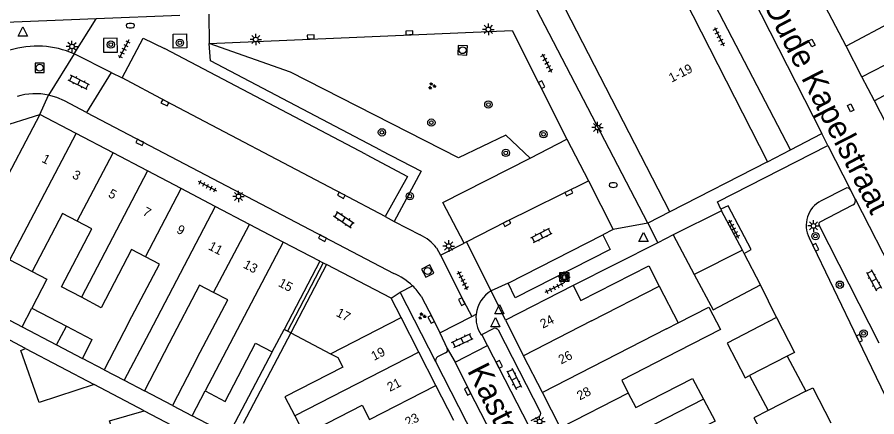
# Model space of a CAD drawing. Extents: x 132999 to 136000, y 398499 to 400501.
# Drawn here: x 133414.1 to 133507.8, y 398557.3 to 398600.8 of the extents above; entities that cross this region are included whole.
import ezdxf

# ---------------------------------------------------------------- set-up
doc = ezdxf.new("R2010")
doc.units = 0
for name, color, linetype in [('gg-afsc-erfafscheiding', 7, 'Continuous'), ('gg-afsc-muur', 7, 'Continuous'), ('gg-anno-huisnummerreeks BGT', 7, 'Continuous'), ('gg-anno-openbare ruimte label', 7, 'Continuous'), ('gg-bbg-bijgebouw', 7, 'Continuous'), ('gg-bbg-gedigitaliseerde bebouwing', 7, 'Continuous'), ('gg-bbg-gedigitaliseerde bebouwing onder overbouw', 7, 'Continuous'), ('gg-bbg-gedigitaliseerde bijgebouw', 7, 'Continuous'), ('gg-bbg-gedigitaliseerde overbouw', 7, 'Continuous'), ('gg-bbg-hoofdgebouw', 7, 'Continuous'), ('gg-bbg-pand overbouw', 7, 'Continuous'), ('gg-bbg-tussenscheiding', 7, 'Continuous'), ('gg-bbg-tussenscheiding niveau 01', 7, 'Continuous'), ('gg-knt-verharding', 7, 'Continuous'), ('gg-knt-verharding nz', 7, 'Continuous'), ('gt-grn-groengrens', 7, 'Continuous'), ('gt-grn-weggrens', 7, 'Continuous'), ('gt-symb-boom', 7, 'Continuous'), ('gt-symb-brandkraan', 7, 'Continuous'), ('gt-symb-groenvak', 7, 'Continuous'), ('gt-symb-klinker verharding', 7, 'Continuous'), ('gt-symb-kolk', 7, 'Continuous'), ('gt-symb-kolk center center', 7, 'Continuous'), ('gt-symb-laadpunt elektrisch vervoer', 7, 'Continuous'), ('gt-symb-lichtmast', 7, 'Continuous'), ('gt-symb-rioolschacht', 7, 'Continuous'), ('gt-symb-tegel verharding', 7, 'Continuous'), ('gt-symb-waterafsluiter', 7, 'Continuous')]:
    doc.layers.add(name, color=color, linetype=linetype)

# ---------------------------------------------------------------- blocks, each defined once
blk = doc.blocks.new('gt0-KOLK')
at = {"layer": 'gt-symb-kolk'}
blk.add_lwpolyline([(0, 0), (0.375, 0), (0.375, 0.4), (-0.375, 0.4), (-0.375, 0), (0, 0)], dxfattribs=at)
blk = doc.blocks.new('gt0-BOOM')
at = {"layer": 'gt-symb-boom'}
for radius in [0.4, 0.2]:
    blk.add_circle((0, 0), radius, dxfattribs=at)
blk = doc.blocks.new('gt0-KL1')
at = {"layer": 'gt-symb-klinker verharding'}
for p, q in [((-1.15, 0.3), (1.15, 0.3)), ((-1, -0.3), (-1, 0.3)), ((-0.5, 0.3), (-0.5, 0.45)), ((0, -0.3), (0, 0.3)), ((0.5, 0.3), (0.5, 0.45)), ((1, -0.3), (1, 0.3)), ((-1.15, -0.3), (1.15, -0.3)), ((-0.5, -0.45), (-0.5, -0.3)), ((0.5, -0.45), (0.5, -0.3))]:
    blk.add_line(p, q, dxfattribs=at)
blk = doc.blocks.new('gt0-KOLKCC')
at = {"layer": 'gt-symb-kolk center center'}
blk.add_lwpolyline([(-0.375, 0.2), (0.375, 0.2), (0.375, -0.2), (-0.375, -0.2)], close=True, dxfattribs=at)
blk = doc.blocks.new('gt0-LMAST')
at = {"layer": 'gt-symb-lichtmast'}
for p, q in [((-0.182, 0.173), (-0.447, 0.438)), ((-0.005, 0.246), (-0.005, 0.621)), ((0.172, 0.173), (0.437, 0.438)), ((-0.255, -0.004), (-0.63, -0.004)), ((-0.182, -0.181), (-0.447, -0.446)), ((-0.005, -0.254), (-0.005, -0.629)), ((0.437, -0.446), (0.172, -0.181)), ((0.245, -0.004), (0.62, -0.004))]:
    blk.add_line(p, q, dxfattribs=at)
blk.add_circle((-0.005, -0.004), 0.25, dxfattribs=at)
blk = doc.blocks.new('gt0-TEG1')
at = {"layer": 'gt-symb-tegel verharding'}
for p, q in [((-1.125, 0), (1.125, 0)), ((-0.9, -0.25), (-0.9, 0.25)), ((-0.45, -0.25), (-0.45, 0.25)), ((0, -0.25), (0, 0.25)), ((0.45, -0.25), (0.45, 0.25)), ((0.9, -0.25), (0.9, 0.25))]:
    blk.add_line(p, q, dxfattribs=at)
blk = doc.blocks.new('gt0-BR')
at = {"layer": 'gt-symb-brandkraan'}
for centre, radius, start, end in [((-0.244, 0), 0.206, 107.56694, 252.43307), ((0.599, -2.664), 3, 106.89205, 107.56694), ((0, -0.691), 0.938, 73.10799, 106.89205), ((-0.599, -2.664), 3, 72.43309, 73.10799), ((0.244, 0), 0.206, 287.56695, 72.43309), ((0.599, 2.664), 3, 252.43307, 253.10797), ((0, 0.691), 0.938, 253.10797, 286.89206), ((-0.599, 2.664), 3, 286.89206, 287.56695)]:
    blk.add_arc(centre, radius, start, end, dxfattribs=at)
blk = doc.blocks.new('gt0-LEV')
at = {"layer": 'gt-symb-laadpunt elektrisch vervoer'}
blk.add_lwpolyline([(-0.486, 0.501), (0.486, 0.501), (0.486, -0.499), (-0.486, -0.499)], close=True, dxfattribs=at)
for centre, radius in [((0, 0), 0.393), ((-0.186, 0), 0.0566), ((0.186, 0), 0.0566)]:
    blk.add_circle(centre, radius, dxfattribs=at)
blk = doc.blocks.new('gt0-WAFSL')
at = {"layer": 'gt-symb-waterafsluiter'}
for p, q in [((-0.5, -0.333), (0, 0.667)), ((0, 0.667), (0.5, -0.333)), ((0.5, -0.333), (-0.5, -0.333))]:
    blk.add_line(p, q, dxfattribs=at)
blk = doc.blocks.new('gt0-RS')
at = {"layer": 'gt-symb-rioolschacht'}
blk.add_lwpolyline([(-0.5, -0.5), (0.5, -0.5), (0.5, 0.5), (-0.5, 0.5)], close=True, dxfattribs=at)
blk.add_circle((0, 0), 0.375, dxfattribs=at)
blk = doc.blocks.new('gt0-GRVAK')
at = {"layer": 'gt-symb-groenvak'}
for p, q in [((-0.11, 0.189), (-0.228, 0.24)), ((-0.182, 0.153), (0.088, 0.153)), ((-0.091, 0.211), (-0.156, 0.322)), ((-0.047, 0.214), (-0.047, 0.393)), ((-0.004, 0.211), (0.061, 0.322)), ((0.015, 0.189), (0.133, 0.24)), ((0.262, -0.052), (0.197, 0.059)), ((0.305, -0.049), (0.305, 0.13)), ((0.349, -0.052), (0.414, 0.059)), ((-0.245, -0.228), (-0.363, -0.177)), ((-0.318, -0.264), (-0.047, -0.264)), ((-0.226, -0.206), (-0.291, -0.095)), ((-0.183, -0.203), (-0.183, -0.024)), ((-0.139, -0.206), (-0.074, -0.095)), ((-0.12, -0.228), (-0.002, -0.177)), ((0.243, -0.074), (0.125, -0.023)), ((0.17, -0.11), (0.441, -0.11)), ((0.368, -0.074), (0.486, -0.023))]:
    blk.add_line(p, q, dxfattribs=at)

msp = doc.modelspace()

# ---------------------------------------------------------------- linework, layer by layer
at = {"layer": 'gg-afsc-erfafscheiding'}
for p, q in [((133496.864, 398568.116), (133495.101, 398571.685)), ((133415.05, 398564.747), (133412.188, 398566.229)), ((133443.93, 398566.44), (133438.756, 398556.569)), ((133423.598, 398562.427), (133421.228, 398563.669)), ((133427.963, 398557.961), (133422.517, 398560.804)), ((133431.042, 398558.525), (133427.982, 398560.129))]:
    msp.add_line(p, q, dxfattribs=at)
msp.add_lwpolyline([(133441.908, 398564.38), (133437.152, 398555.322), (133433.201, 398557.393)], dxfattribs=at)
at = {"layer": 'gg-afsc-muur'}
for p, q in [((133485.6, 398577.111), (133483.915, 398576.258)), ((133483.915, 398576.258), (133474.71, 398571.6))]:
    msp.add_line(p, q, dxfattribs=at)
at = {"layer": 'gg-bbg-bijgebouw'}
for p, q in [((133504.434, 398597.688), (133501.806, 398602.758)), ((133506.163, 398594.351), (133504.434, 398597.688)), ((133507.525, 398591.723), (133506.163, 398594.351)), ((133508.838, 398589.189), (133507.525, 398591.723)), ((133490.88, 398579.751), (133485.6, 398577.111)), ((133493.16, 398575.439), (133490.88, 398579.751)), ((133493.329, 398575.112), (133493.16, 398575.439)), ((133495.101, 398571.685), (133493.329, 398575.112)), ((133498.4, 398564.084), (133498.034, 398563.894)), ((133498.034, 398563.894), (133500.043, 398560.076))]:
    msp.add_line(p, q, dxfattribs=at)
for points in [[(133496.864, 398568.116), (133498.838, 398564.31), (133498.4, 398564.084)], [(133500.043, 398560.076), (133500.831, 398560.459), (133502.781, 398556.636)]]:
    msp.add_lwpolyline(points, dxfattribs=at)
at = {"layer": 'gg-bbg-gedigitaliseerde bebouwing'}
for p, q in [((133482.95, 398573.761), (133484.09, 398571.541)), ((133484.09, 398571.541), (133486.141, 398567.538)), ((133426.31, 398567.607), (133423.598, 398562.427)), ((133441.908, 398564.38), (133443.2, 398566.823)), ((133443.93, 398566.44), (133448.271, 398564.168)), ((133430.694, 398565.311), (133427.982, 398560.129)), ((133433.756, 398563.709), (133431.042, 398558.525)), ((133423.598, 398562.427), (133425.786, 398561.28)), ((133425.786, 398561.28), (133427.982, 398560.129)), ((133433.201, 398557.393), (133434.628, 398560.115)), ((133431.042, 398558.525), (133433.201, 398557.393))]:
    msp.add_line(p, q, dxfattribs=at)
for points in [[(133420.672, 398578.613), (133419.071, 398579.451), (133415.761, 398573.127)], [(133421.126, 398570.319), (133418.963, 398571.451), (133422.273, 398577.775), (133420.672, 398578.613)], [(133428.11, 398574.721), (133426.599, 398575.512), (133423.288, 398569.187), (133421.126, 398570.319)], [(133426.31, 398567.607), (133429.621, 398573.93), (133428.11, 398574.721)], [(133435.536, 398570.835), (133434.006, 398571.636), (133430.694, 398565.311)], [(133433.756, 398563.709), (133437.067, 398570.033), (133435.536, 398570.835)], [(133486.141, 398567.538), (133489.5, 398569.26), (133490.761, 398566.801), (133486.153, 398564.438)], [(133434.628, 398560.115), (133436.792, 398558.981), (133440.111, 398565.321), (133441.908, 398564.38)], [(133486.153, 398564.438), (133479.997, 398561.283), (133480.712, 398559.888)], [(133448.271, 398564.168), (133449.076, 398563.747), (133449.611, 398562.703), (133443.303, 398559.47), (133444.364, 398557.399)], [(133480.712, 398559.888), (133481.528, 398558.296), (133487.722, 398561.471), (133488.912, 398559.222)], [(133488.912, 398559.222), (133490.176, 398556.831), (133483.922, 398553.626), (133484.657, 398552.192)], [(133444.364, 398557.399), (133445.426, 398555.328), (133451.732, 398558.56), (133452.532, 398557)]]:
    msp.add_lwpolyline(points, dxfattribs=at)
at = {"layer": 'gg-bbg-gedigitaliseerde bebouwing onder overbouw'}
for p, q in [((133447.09, 398574.251), (133443.2, 398566.823)), ((133447.84, 398573.911), (133443.93, 398566.44))]:
    msp.add_line(p, q, dxfattribs=at)
at = {"layer": 'gg-bbg-gedigitaliseerde bijgebouw'}
for p, q in [((133485.6, 398577.111), (133487.89, 398572.821)), ((133415.717, 398569.144), (133419.483, 398567.172)), ((133414.655, 398567.114), (133418.42, 398565.141)), ((133415.05, 398564.747), (133422.517, 398560.804)), ((133418.42, 398565.141), (133421.228, 398563.669)), ((133493.931, 398561.793), (133495.939, 398557.976)), ((133427.963, 398557.961), (133432.477, 398555.595))]:
    msp.add_line(p, q, dxfattribs=at)
for points in [[(133415.761, 398573.127), (133417.363, 398572.289), (133415.717, 398569.144)], [(133487.89, 398572.821), (133489.961, 398568.941), (133495.101, 398571.685)], [(133410.783, 398569.518), (133410.631, 398569.224), (133414.655, 398567.114)], [(133496.864, 398568.116), (133491.491, 398565.329), (133493.452, 398561.548), (133493.931, 398561.793)], [(133419.483, 398567.172), (133422.265, 398565.717), (133421.228, 398563.669)], [(133422.517, 398560.804), (133416.54, 398558.864), (133414.517, 398564.537), (133415.05, 398564.747)], [(133428.582, 398554.399), (133425.267, 398553.381), (133424.178, 398556.842), (133427.963, 398557.961)], [(133495.939, 398557.976), (133494.405, 398557.192), (133496.418, 398553.369)]]:
    msp.add_lwpolyline(points, dxfattribs=at)
at = {"layer": 'gg-bbg-gedigitaliseerde overbouw'}
for p, q in [((133443.565, 398566.632), (133443.2, 398566.823)), ((133443.93, 398566.44), (133443.565, 398566.632))]:
    msp.add_line(p, q, dxfattribs=at)
at = {"layer": 'gg-bbg-hoofdgebouw'}
for p, q in [((133485.23, 398579.62), (133471.65, 398606.041)), ((133416.597, 398590.258), (133409.788, 398577.287)), ((133420.484, 398588.218), (133416.597, 398590.258)), ((133420.552, 398588.182), (133420.484, 398588.218)), ((133424.575, 398586.07), (133420.552, 398588.182)), ((133428.338, 398584.095), (133424.575, 398586.07)), ((133495.89, 398585.081), (133485.23, 398579.62)), ((133432.008, 398582.169), (133428.338, 398584.095)), ((133435.711, 398580.225), (133432.008, 398582.169)), ((133439.431, 398578.272), (133435.711, 398580.225)), ((133443.122, 398576.334), (133439.431, 398578.272)), ((133447.09, 398574.251), (133443.122, 398576.334)), ((133454.88, 398570.221), (133447.84, 398573.911)), ((133474.71, 398571.6), (133467.32, 398567.811)), ((133455.963, 398568.107), (133454.88, 398570.221)), ((133457.895, 398564.334), (133455.963, 398568.107)), ((133467.32, 398567.811), (133469.294, 398563.96)), ((133459.754, 398560.703), (133457.895, 398564.334)), ((133471.348, 398559.955), (133469.294, 398563.96)), ((133461.702, 398556.899), (133459.754, 398560.703)), ((133473.324, 398556.101), (133471.348, 398559.955))]:
    msp.add_line(p, q, dxfattribs=at)
for points in [[(133485.137, 398608.828), (133485.22, 398608.671), (133484.14, 398608.13), (133495.89, 398585.081)], [(133474.71, 398571.6), (133475.54, 398569.971), (133482.95, 398573.761)]]:
    msp.add_lwpolyline(points, dxfattribs=at)
at = {"layer": 'gg-bbg-pand overbouw'}
for p, q in [((133447.09, 398574.251), (133447.465, 398574.081)), ((133447.465, 398574.081), (133447.84, 398573.911))]:
    msp.add_line(p, q, dxfattribs=at)
at = {"layer": 'gg-bbg-tussenscheiding'}
for p, q in [((133509.644, 398600.448), (133504.434, 398597.688)), ((133506.163, 398594.351), (133511.399, 398597.065)), ((133512.715, 398594.558), (133507.525, 398591.723)), ((133413.322, 398574.407), (133420.552, 398588.182)), ((133420.672, 398578.613), (133424.575, 398586.07)), ((133428.338, 398584.095), (133421.126, 398570.319)), ((133428.11, 398574.721), (133432.008, 398582.169)), ((133435.711, 398580.225), (133428.502, 398566.459)), ((133435.536, 398570.835), (133439.431, 398578.272)), ((133443.122, 398576.334), (133434.628, 398560.115)), ((133493.16, 398575.439), (133487.89, 398572.821)), ((133413.322, 398574.407), (133415.761, 398573.127)), ((133476.686, 398567.747), (133484.09, 398571.541)), ((133414.655, 398567.114), (133415.717, 398569.144)), ((133448.271, 398564.168), (133455.963, 398568.107)), ((133418.42, 398565.141), (133419.483, 398567.172)), ((133476.686, 398567.747), (133469.294, 398563.96)), ((133484.861, 398566.882), (133486.141, 398567.538)), ((133428.502, 398566.459), (133425.786, 398561.28)), ((133484.861, 398566.882), (133471.348, 398559.955)), ((133457.895, 398564.334), (133444.364, 398557.399)), ((133498.034, 398563.894), (133493.931, 398561.793)), ((133452.532, 398557), (133459.754, 398560.703)), ((133480.712, 398559.888), (133473.324, 398556.101)), ((133500.043, 398560.076), (133495.939, 398557.976)), ((133488.912, 398559.222), (133475.299, 398552.248))]:
    msp.add_line(p, q, dxfattribs=at)
at = {"layer": 'gg-bbg-tussenscheiding niveau 01'}
msp.add_line((133447.465, 398574.081), (133443.565, 398566.632), dxfattribs=at)
at = {"layer": 'gg-knt-verharding'}
for p, q in [((133490.822, 398609.699), (133501.806, 398588.153)), ((133498.38, 398586.391), (133487.216, 398607.907)), ((133482.83, 398578.401), (133470.246, 398602.631)), ((133431.86, 398601.031), (133422.725, 398600.661)), ((133422.725, 398600.661), (133390.33, 398599.351)), ((133452.161, 398585.892), (133430.173, 398597.438)), ((133420.345, 398596.841), (133417.553, 398592.36)), ((133424.364, 398594.835), (133420.345, 398596.841)), ((133424.364, 398594.835), (133421.683, 398590.477)), ((133424.364, 398594.835), (133425.579, 398594.225)), ((133411.38, 398588.591), (133416.597, 398590.258)), ((133421.683, 398590.477), (133455.15, 398572.92)), ((133498.38, 398586.391), (133501.806, 398588.153)), ((133502.47, 398586.851), (133501.806, 398588.153)), ((133470.038, 398585.499), (133474.031, 398587.536)), ((133474.031, 398587.536), (133476.364, 398583)), ((133476.364, 398583), (133479.076, 398577.725)), ((133504.363, 398582.192), (133501.728, 398580.843)), ((133505.421, 398581.054), (133504.93, 398582.041)), ((133501.63, 398578.543), (133505.192, 398580.404)), ((133485.23, 398579.62), (133482.83, 398578.401)), ((133490.797, 398579.933), (133490.88, 398579.751)), ((133454.224, 398579.112), (133455.219, 398578.593)), ((133455.219, 398578.593), (133458.043, 398577.12)), ((133479.076, 398577.725), (133477.951, 398577.124)), ((133508.038, 398565.332), (133501.492, 398578.176)), ((133459.81, 398575.694), (133460.256, 398574.917)), ((133460.256, 398574.917), (133462.842, 398576.23)), ((133463.101, 398576.368), (133462.842, 398576.23)), ((133465.787, 398571.027), (133463.101, 398576.368)), ((133467.614, 398571.847), (133465.787, 398571.027)), ((133455.865, 398570.892), (133457.203, 398571.576)), ((133459.754, 398563.28), (133455.865, 398570.892)), ((133460.17, 398566.446), (133463.651, 398568.232)), ((133463.651, 398568.232), (133464.129, 398568.477)), ((133460.17, 398566.446), (133460.993, 398564.753)), ((133464.695, 398566.239), (133464.758, 398566.271)), ((133464.758, 398566.271), (133466.041, 398566.927)), ((133465.374, 398565.07), (133464.758, 398566.271)), ((133466.537, 398566.758), (133471.121, 398557.824)), ((133460.993, 398564.753), (133461.834, 398563.255)), ((133461.834, 398563.255), (133465.374, 398565.07)), ((133469.887, 398556.296), (133465.374, 398565.07)), ((133460.811, 398564.257), (133459.929, 398563.82)), ((133472.307, 398538.755), (133459.754, 398563.28)), ((133470.956, 398557.297), (133470.086, 398556.851))]:
    msp.add_line(p, q, dxfattribs=at)
for points in [[(133431.118, 398598.978), (133432.593, 398599.016), (133432.603, 398597.504), (133431.128, 398597.465), (133431.118, 398598.978)], [(133435.03, 398597.981), (133468.05, 398599.38), (133474.031, 398587.536)], [(133423.525, 398598.534), (133423.533, 398597.034), (133425.047, 398597.043), (133425.038, 398598.543), (133423.525, 398598.534)], [(133425.579, 398594.225), (133427.855, 398598.563), (133430.173, 398597.438)], [(133453.77, 398586.311), (133435.19, 398596.091), (133435.03, 398597.981)], [(133421.683, 398590.477), (133419.282, 398591.736), (133418.439, 398592.107), (133417.553, 398592.36)], [(133490.797, 398579.933), (133490.44, 398580.721), (133502.47, 398586.851)], [(133452.161, 398585.892), (133456.638, 398583.495), (133454.224, 398579.112)], [(133453.77, 398586.311), (133458.162, 398584.053), (133455.219, 398578.593)], [(133462.842, 398576.23), (133460.52, 398580.642), (133470.038, 398585.499)], [(133493.329, 398575.112), (133494.112, 398575.517), (133491.608, 398580.301), (133490.797, 398579.933)], [(133477.951, 398577.124), (133478.754, 398575.538), (133468.391, 398570.251), (133467.614, 398571.847)], [(133500.419, 398576.789), (133505.719, 398565.76), (133514.738, 398547.082)], [(133460.256, 398574.917), (133462.745, 398569.939), (133463.651, 398568.232)], [(133458.151, 398570.446), (133459.414, 398568.01), (133460.17, 398566.446)], [(133461.834, 398563.255), (133463.377, 398560.179), (133469.504, 398548.244)]]:
    msp.add_lwpolyline(points, dxfattribs=at)
for centre, radius, start, end in [((133416.292, 398587.661), 10.035, 66.17911, 107.18179), ((133416.134, 398585.719), 6.791, 77.93943, 107.23388), ((133504.566, 398581.814), 0.429, 31.98989, 118.18502), ((133503.115, 398578.157), 3.023, 117.31466, 206.89574), ((133504.966, 398580.849), 0.499, 296.93021, 24.25428), ((133501.733, 398578.295), 0.269, 112.55311, 206.23218), ((133455.997, 398572.777), 4.8, 37.41561, 64.77611), ((133452.565, 398566.731), 6.707, 46.24922, 67.32911), ((133452.543, 398566.704), 6.742, 33.71425, 46.27489), ((133467.459, 398568.126), 3.348, 119.9543, 173.98217), ((133467.46, 398568.129), 3.349, 174.03268, 214.35283), ((133466.165, 398566.479), 0.465, 36.90652, 105.46287), ((133460.645, 398564.599), 0.381, 295.88957, 23.81067), ((133460.121, 398563.459), 0.409, 118.05135, 206.03632), ((133470.783, 398557.64), 0.384, 296.68154, 28.54852)]:
    msp.add_arc(centre, radius, start, end, dxfattribs=at)
at = {"layer": 'gg-knt-verharding nz'}
for p, q in [((133505.421, 398581.054), (133512.456, 398567.285)), ((133467.614, 398571.847), (133477.951, 398577.124))]:
    msp.add_line(p, q, dxfattribs=at)
for points in [[(133454.224, 398579.112), (133449.548, 398581.614), (133430.312, 398591.703), (133425.579, 398594.225)], [(133463.101, 398576.368), (133467.398, 398578.568), (133476.364, 398583)]]:
    msp.add_lwpolyline(points, dxfattribs=at)
at = {"layer": 'gt-grn-groengrens'}
msp.add_lwpolyline([(133470.038, 398585.499), (133467.365, 398587.976), (133462.22, 398585.532), (133443.897, 398594.857), (133435.03, 398597.981)], dxfattribs=at)
at = {"layer": 'gt-grn-weggrens'}
for p, q in [((133435, 398601.161), (133435.03, 398597.981)), ((133420.345, 398596.841), (133422.725, 398600.661)), ((133416.597, 398590.258), (133417.553, 398592.36)), ((133502.47, 398586.851), (133504.93, 398582.041)), ((133495.89, 398585.081), (133498.38, 398586.391)), ((133482.83, 398578.401), (133479.076, 398577.725)), ((133482.83, 398578.401), (133483.915, 398576.258)), ((133454.88, 398570.221), (133455.865, 398570.892)), ((133467.32, 398567.811), (133465.787, 398571.027))]:
    msp.add_line(p, q, dxfattribs=at)

# ---------------------------------------------------------------- block references
at = {"layer": 'gt-symb-boom'}
for p in [(133424.327, 398597.859), (133431.853, 398598.055), (133465.468, 398591.321), (133459.255, 398589.359), (133453.87, 398588.296), (133471.483, 398588.087), (133467.364, 398586.055), (133456.908, 398581.337), (133501.108, 398576.99), (133503.762, 398571.695), (133506.354, 398566.387)]:
    msp.add_blockref('gt0-BOOM', p, dxfattribs=at)
at = {"layer": 'gt-symb-brandkraan'}
for p in [(133426.457, 398599.929), (133479.07, 398582.551)]:
    msp.add_blockref('gt0-BR', p, dxfattribs=at)
at = {"layer": 'gt-symb-groenvak', "rotation": 3.2116257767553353}
msp.add_blockref('gt0-GRVAK', (133459.306, 398593.357), dxfattribs=at)
at = {"layer": 'gt-symb-groenvak'}
msp.add_blockref('gt0-GRVAK', (133458.227, 398568.262), dxfattribs=at)
at = {"layer": 'gt-symb-klinker verharding'}
for p, rotation in [((133420.844, 398593.739), 153.33249782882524), ((133449.726, 398578.794), -33.70595653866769), ((133471.258, 398577.07), 27.128766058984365), ((133507.472, 398572.19), -61.179164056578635), ((133462.626, 398565.608), 24.847205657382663), ((133468.276, 398561.432), -63.20443508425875)]:
    msp.add_blockref('gt0-KL1', p, dxfattribs=dict(at, rotation=rotation))
at = {"layer": 'gt-symb-kolk'}
for p, rotation in [((133456.862, 398598.95), 2.3501595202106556), ((133446.117, 398598.492), 2.407413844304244), ((133471.09, 398593.41), -62.99934529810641), ((133430.312, 398591.703), 152.23078730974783), ((133427.582, 398587.383), 152.28149837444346), ((133449.548, 398581.614), 151.8466534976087), ((133474.141, 398581.897), -153.38370037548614), ((133467.397, 398578.568), -152.87123394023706), ((133447.484, 398576.944), 152.358857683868), ((133500.954, 398575.681), -64.2181420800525), ((133462.745, 398569.939), 116.56505117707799), ((133459.414, 398568.01), 117.40598339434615), ((133505.719, 398565.76), -64.34444382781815), ((133466.479, 398562.915), -62.76010532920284), ((133463.377, 398560.179), 116.63361698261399)]:
    msp.add_blockref('gt0-KOLK', p, dxfattribs=dict(at, rotation=rotation))
at = {"layer": 'gt-symb-kolk center center'}
for p, rotation in [((133500.704, 398598.024), -61.66262373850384), ((133504.953, 398590.969), -63.51182146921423)]:
    msp.add_blockref('gt0-KOLKCC', p, dxfattribs=dict(at, rotation=rotation))
at = {"layer": 'gt-symb-laadpunt elektrisch vervoer'}
msp.add_blockref('gt0-LEV', (133473.732, 398572.537), dxfattribs=at)
at = {"layer": 'gt-symb-lichtmast'}
for p in [(133465.473, 398599.521), (133440.125, 398598.42), (133420.105, 398597.654), (133477.37, 398588.822), (133438.248, 398581.318), (133500.9, 398578.102), (133461.15, 398575.913), (133473.744, 398572.52), (133471.05, 398556.792)]:
    msp.add_blockref('gt0-LMAST', p, dxfattribs=at)
at = {"layer": 'gt-symb-rioolschacht'}
for p, rotation in [((133462.662, 398597.249), -92.80805306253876), ((133458.862, 398573.179), 116.92362535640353)]:
    msp.add_blockref('gt0-RS', p, dxfattribs=dict(at, rotation=rotation))
msp.add_blockref('gt0-RS', (133416.57, 398595.335), dxfattribs=at)
at = {"layer": 'gt-symb-tegel verharding'}
for p, rotation in [((133490.606, 398598.734), -62.99934529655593), ((133425.766, 398597.368), -117.69186801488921), ((133471.832, 398595.856), -62.99934529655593), ((133434.858, 398582.438), -27.718501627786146), ((133492.21, 398577.772), -62.15337781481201), ((133462.675, 398572.138), 116.92362535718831), ((133472.638, 398571.352), -152.87123394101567)]:
    msp.add_blockref('gt0-TEG1', p, dxfattribs=dict(at, rotation=rotation))
at = {"layer": 'gt-symb-waterafsluiter'}
for p in [(133414.749, 398599.114), (133482.37, 398576.732), (133466.669, 398568.863), (133466.233, 398567.445)]:
    msp.add_blockref('gt0-WAFSL', p, dxfattribs=at)

# ---------------------------------------------------------------- texts
at = {"layer": 'gg-anno-huisnummerreeks BGT'}
for s, rotation, p in [('1-19', 27, (133485.431, 398593.711)), ('1', 332.3, (133416.722, 398585.11)), ('3', 332.3, (133420.041, 398583.368)), ('5', 332.3, (133423.968, 398581.306)), ('7', 332.3, (133427.72, 398579.337)), ('9', 332.3, (133431.404, 398577.404)), ('11', 332.3, (133434.873, 398575.581)), ('13', 332.3, (133438.673, 398573.587)), ('15', 332.3, (133442.502, 398571.576)), ('17', 332.4, (133448.796, 398568.328)), ('24', 27.1, (133471.411, 398566.894)), ('19', 27.1, (133453.012, 398563.388)), ('26', 27.1, (133473.408, 398562.999)), ('21', 27.1, (133454.743, 398560.008)), ('28', 27.1, (133475.423, 398559.07)), ('23', 27.1, (133456.695, 398556.196))]:
    msp.add_text(s, height=1, rotation=rotation, dxfattribs=at).set_placement(p)
at = {"layer": 'gg-anno-openbare ruimte label'}
for s, rotation, p in [('Oude Kapelstraat', 297.1, (133495.358, 398602.347)), ('Kasteeldreef', 296.9, (133463.112, 398562.334))]:
    msp.add_text(s, height=2.5, rotation=rotation, dxfattribs=at).set_placement(p)

doc.saveas('drawing.dxf')
